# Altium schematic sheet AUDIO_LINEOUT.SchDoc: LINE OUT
size A4; Author: Silvio Navaretti; CompanyName: Arduino SRL; DrawnBy: Silvio Navaretti; Engineer: Silvio Navaretti; Organization: Arduino SRL; DocumentNumber: ASX00083; SheetNumber: 10; SheetTotal: 11; RevAuthor: Silvio Navaretti
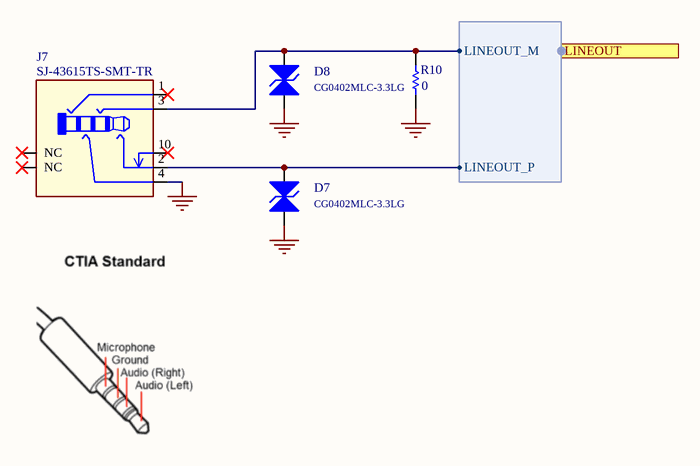
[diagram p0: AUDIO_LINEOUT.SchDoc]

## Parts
D7  CG0402MLC-3.3LG  [0402]
D8  CG0402MLC-3.3LG  [0402]
J7  SJ-43615TS-SMT-TR  [SJ-43615TS-SMT-TR]
R10  value 0  [RES-0402]  (hidden comment: CRCW04020000Z0EDC)

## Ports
LINEOUT (harness LINEOUT)

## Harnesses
LINEOUT: LINEOUT_P, LINEOUT_M

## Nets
GND: D7.A D8.A J7.4 R10.1
NetD7_C: D7.C J7.2 ; port LINEOUT.LINEOUT_P
NetD8_C: D8.C J7.3 R10.2 ; port LINEOUT.LINEOUT_M

Not connected (* = marked no-connect by the designer): J7 1* 10* 11(NC)* 12(NC)*

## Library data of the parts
D7 D8 = D0073-A.3: DIODE TVS SMD 0402 3.3V ESD PROTECTION; Manufacturer: Bourns; Code Arduino: D0073; Direction: Bidirectional
J7 = J0533-A.9: CONN Audio Jack 3.5mm, 4 conductor, tip switch, SMD mid mount; Manufacturer: Same Sky; Code Arduino: J0533
R10 = R0000-A.24: RES CHIP 0402 0R 1/16W; Manufacturer: Vishay; Code Arduino: 0039; Power: 62.5mW; Tolerance: 0%; Temperature coefficient: 0ppm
